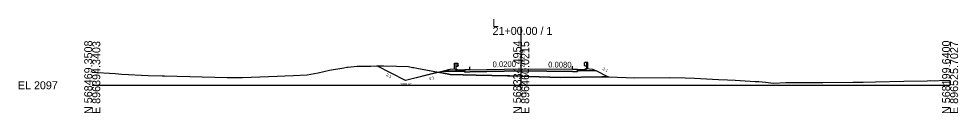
# Model space of a CAD drawing. Extents: x -26 to 1603, y -10 to 13527.
# Drawn here: x -25.7 to 302.8, y 8490.3 to 8523.1 of the extents above; entities that cross this region are included whole.
import ezdxf

# ---------------------------------------------------------------- set-up
doc = ezdxf.new("R2010")
doc.units = 0
for name, color, linetype in [('Default', 7, 'Continuous'), ('Exist XS Center Line Elevation Label', 7, 'Continuous'), ('Exist XS Ground Line', 7, 'Continuous'), ('Old_Level_3', 7, 'Continuous'), ('Old_Level_63', 7, 'Continuous'), ('Prop XS Ditch Slope Text', 7, 'Continuous'), ('Prop XS Ditch Standard Text', 7, 'Continuous'), ('Prop XS Dump Level', 7, 'Continuous'), ('Prop XS Earthwork Shape', 7, 'Continuous'), ('Prop XS EOT Tick Mark', 7, 'Continuous'), ('Prop XS Finish Grade', 7, 'Continuous'), ('Prop XS Finish Grade Earthwork', 7, 'Continuous'), ('Prop XS Finish Grade Paved Shoulder', 7, 'Continuous'), ('Prop XS Finish Grade Pavement', 7, 'Continuous'), ('Prop XS Side Slope Text', 7, 'Continuous'), ('Prop XS Subgrade Earthwork', 7, 'Continuous'), ('Prop XSC Text', 7, 'Continuous'), ('Typical Curb CELL', 7, 'Continuous')]:
    doc.layers.add(name, color=color, linetype=linetype)

msp = doc.modelspace()

# ---------------------------------------------------------------- linework, layer by layer
at = {"layer": 'Exist XS Ground Line'}
for p, q in [((82.97, 8505.32), (87.93, 8506.08)), ((87.93, 8506.08), (89.03, 8506.27)), ((89.03, 8506.27), (89.42, 8506.31)), ((89.42, 8506.31), (92.6, 8506.63)), ((92.6, 8506.63), (97.43, 8506.7)), ((97.43, 8506.7), (101.89, 8506.78)), ((101.89, 8506.78), (106.44, 8506.64)), ((106.44, 8506.64), (110.56, 8506.53)), ((110.56, 8506.53), (111.94, 8506.25)), ((111.94, 8506.25), (112.48, 8506.18)), ((112.48, 8506.18), (113.47, 8505.99)), ((113.47, 8505.99), (124.68, 8503.87)), ((0, 8504.61), (7.96, 8504.08)), ((7.96, 8504.08), (10.31, 8503.93)), ((10.31, 8503.93), (19.57, 8503.37)), ((19.57, 8503.37), (24.45, 8503.26)), ((24.45, 8503.26), (25.24, 8503.27)), ((25.24, 8503.27), (34.16, 8503.11)), ((34.16, 8503.11), (47.13, 8502.77)), ((47.13, 8502.77), (51.05, 8502.68)), ((51.05, 8502.68), (52.55, 8502.7)), ((52.55, 8502.7), (64.69, 8503.17)), ((64.69, 8503.17), (67.3, 8503.28)), ((67.3, 8503.28), (70.39, 8503.36)), ((70.39, 8503.36), (75.14, 8503.62)), ((75.14, 8503.62), (79, 8504.4)), ((79, 8504.4), (82.97, 8505.32)), ((124.68, 8503.87), (125.21, 8503.78)), ((125.21, 8503.78), (134.25, 8503.48)), ((134.25, 8503.48), (145.2, 8503.35)), ((145.2, 8503.35), (146.09, 8503.33)), ((146.09, 8503.33), (150, 8503.2)), ((150, 8503.2), (152.43, 8503.12)), ((152.43, 8503.12), (163.84, 8502.75)), ((163.84, 8502.75), (178.16, 8502.92)), ((178.16, 8502.92), (180.73, 8502.94)), ((180.73, 8502.94), (189.6, 8502.58)), ((189.6, 8502.58), (201.79, 8502.77)), ((201.79, 8502.77), (207.36, 8502.65)), ((207.36, 8502.65), (210.62, 8502.47)), ((210.62, 8502.47), (219.05, 8502.05)), ((219.05, 8502.05), (222.15, 8501.85)), ((222.15, 8501.85), (224.89, 8501.8)), ((224.89, 8501.8), (231.79, 8501.3)), ((231.79, 8501.3), (233.16, 8501.27)), ((233.16, 8501.27), (235.39, 8501.14)), ((235.39, 8501.14), (238.28, 8500.78)), ((238.28, 8500.78), (242.61, 8500.94)), ((242.61, 8500.94), (248.5, 8500.96)), ((248.5, 8500.96), (254.57, 8501.03)), ((254.57, 8501.03), (255.44, 8501.01)), ((255.44, 8501.01), (266.02, 8501.08)), ((266.02, 8501.08), (269.58, 8501.12)), ((269.58, 8501.12), (273.97, 8501.2)), ((273.97, 8501.2), (283.86, 8501.39)), ((283.86, 8501.39), (291.93, 8501.54)), ((291.93, 8501.54), (293.18, 8501.64)), ((293.18, 8501.64), (294.61, 8501.6)), ((294.61, 8501.6), (297.8, 8501.77)), ((297.8, 8501.77), (300, 8501.67))]:
    msp.add_line(p, q, dxfattribs=at)
at = {"layer": 'Old_Level_3'}
for p, q in [((126.69, 8505.62), (126.69, 8507.73)), ((126.69, 8507.73), (127.19, 8507.73)), ((127.19, 8507.73), (127.19, 8505.65)), ((127.19, 8507.73), (127.69, 8507.73)), ((127.69, 8506.59), (127.19, 8506.59)), ((127.69, 8507.73), (127.98, 8507.53)), ((127.98, 8507.41), (127.69, 8507.21)), ((127.69, 8507.21), (127.69, 8507.11)), ((127.69, 8507.11), (127.98, 8506.91)), ((127.98, 8506.79), (127.69, 8506.59)), ((127.98, 8507.53), (128.01, 8507.47)), ((128.01, 8507.47), (127.98, 8507.41)), ((127.98, 8506.91), (128.01, 8506.85)), ((128.01, 8506.85), (127.98, 8506.79)), ((172.02, 8507.72), (171.99, 8507.66)), ((171.99, 8507.66), (172.02, 8507.6)), ((172.02, 8507.11), (171.99, 8507.05)), ((171.99, 8507.05), (172.02, 8506.99)), ((172.31, 8507.92), (172.02, 8507.72)), ((172.02, 8507.6), (172.31, 8507.4)), ((172.31, 8507.31), (172.02, 8507.11)), ((172.02, 8506.99), (172.31, 8506.79)), ((172.81, 8507.92), (172.31, 8507.92)), ((172.31, 8507.4), (172.31, 8507.31)), ((172.31, 8506.79), (172.81, 8506.79)), ((173.31, 8507.92), (172.81, 8507.92)), ((172.81, 8507.92), (172.81, 8505.8)), ((173.31, 8505.77), (173.31, 8507.92))]:
    msp.add_line(p, q, dxfattribs=at)
at = {"layer": 'Old_Level_63'}
for p, q in [((150, 8500), (150, 8520.34)), ((0, 8500), (150, 8500)), ((150, 8500), (300, 8500))]:
    msp.add_line(p, q, dxfattribs=at)
at = {"layer": 'Prop XS Earthwork Shape'}
for points in [[(121.12, 8504.55), (109.6, 8501.67), (99.47, 8506.73), (101.89, 8506.78), (106.44, 8506.64), (110.56, 8506.53), (111.94, 8506.25), (112.48, 8506.18), (113.47, 8505.99)], [(127.32, 8504.98), (130.34, 8504.98), (130.35, 8504.61), (132, 8504.64), (150, 8505), (168, 8504.85), (169.66, 8504.82), (169.66, 8505.2), (172.68, 8505.13), (176.08, 8505.13), (180.46, 8502.94), (178.16, 8502.92), (163.84, 8502.75), (152.43, 8503.12), (150, 8503.2), (146.09, 8503.33), (145.2, 8503.35), (134.25, 8503.48), (125.21, 8503.78), (124.68, 8503.87), (121.12, 8504.55), (122.85, 8504.98)]]:
    msp.add_lwpolyline(points, close=True, dxfattribs=at)
at = {"layer": 'Prop XS EOT Tick Mark'}
for p, q in [((132, 8505.43), (132, 8506.43)), ((132, 8505.43), (132, 8506.43)), ((168, 8505.65), (168, 8506.65)), ((168, 8505.65), (168, 8506.65)), ((168, 8505.65), (168, 8506.65)), ((168, 8505.65), (168, 8506.65)), ((168, 8505.65), (168, 8506.65))]:
    msp.add_line(p, q, dxfattribs=at)
at = {"layer": 'Prop XS Finish Grade'}
for p, q in [((172.7, 8505.81), (175, 8505.67)), ((125, 8505.52), (122.85, 8504.98)), ((127.32, 8505.66), (125, 8505.52)), ((128.01, 8505.31), (127.32, 8505.66)), ((175, 8505.67), (176.08, 8505.13))]:
    msp.add_line(p, q, dxfattribs=at)
at = {"layer": 'Prop XS Finish Grade Earthwork'}
for p, q in [((109.6, 8501.67), (99.47, 8506.73)), ((122.85, 8504.98), (109.6, 8501.67)), ((176.08, 8505.13), (180.46, 8502.94))]:
    msp.add_line(p, q, dxfattribs=at)
at = {"layer": 'Prop XS Finish Grade Paved Shoulder'}
for p, q in [((132, 8505.43), (130.33, 8505.4)), ((168, 8505.65), (169.67, 8505.61))]:
    msp.add_line(p, q, dxfattribs=at)
at = {"layer": 'Prop XS Finish Grade Pavement'}
for p, q in [((132, 8505.43), (150, 8505.79)), ((150, 8505.79), (168, 8505.65))]:
    msp.add_line(p, q, dxfattribs=at)
at = {"layer": 'Prop XS Subgrade Earthwork'}
for p, q in [((127.32, 8504.98), (122.85, 8504.98)), ((127.32, 8504.98), (130.34, 8504.98)), ((130.35, 8504.61), (130.34, 8504.98)), ((132, 8504.64), (130.35, 8504.61)), ((150, 8505), (132, 8504.64)), ((168, 8504.85), (150, 8505)), ((168, 8504.85), (169.66, 8504.82)), ((169.66, 8505.2), (169.66, 8504.82)), ((169.66, 8505.2), (172.68, 8505.13)), ((172.68, 8505.13), (176.08, 8505.13))]:
    msp.add_line(p, q, dxfattribs=at)
at = {"layer": 'Typical Curb CELL'}
for p, q in [((172, 8505.48), (172.7, 8505.81)), ((172.68, 8505.13), (172.7, 8505.81)), ((127.32, 8504.98), (127.32, 8505.66)), ((128.01, 8505.31), (127.32, 8505.66)), ((127.32, 8504.98), (130.34, 8504.98)), ((127.36, 8505.28), (127.51, 8505.32)), ((127.49, 8505.23), (127.36, 8505.28)), ((127.51, 8505.32), (127.49, 8505.23)), ((128.03, 8505.2), (127.92, 8505.12)), ((127.92, 8505.12), (128.09, 8505.08)), ((130.33, 8505.4), (128.01, 8505.31)), ((128.09, 8505.08), (128.03, 8505.2)), ((128.77, 8505.25), (128.73, 8505.14)), ((128.73, 8505.14), (128.85, 8505.13)), ((128.85, 8505.13), (128.77, 8505.25)), ((129.28, 8505.2), (129.17, 8505.12)), ((129.17, 8505.12), (129.34, 8505.08)), ((129.34, 8505.08), (129.28, 8505.2)), ((130.02, 8505.25), (129.98, 8505.14)), ((129.98, 8505.14), (130.1, 8505.13)), ((130.1, 8505.13), (130.02, 8505.25)), ((130.34, 8505.4), (130.34, 8505.4)), ((130.34, 8504.98), (130.34, 8505.39)), ((169.66, 8505.2), (169.67, 8505.6)), ((172.68, 8505.13), (169.66, 8505.2)), ((169.67, 8505.61), (169.67, 8505.61)), ((169.68, 8505.61), (172, 8505.48)), ((169.9, 8505.34), (169.99, 8505.46)), ((170.02, 8505.35), (169.9, 8505.34)), ((169.99, 8505.46), (170.02, 8505.35)), ((170.67, 8505.27), (170.73, 8505.39)), ((170.83, 8505.31), (170.67, 8505.27)), ((170.73, 8505.39), (170.83, 8505.31)), ((171.15, 8505.31), (171.24, 8505.43)), ((171.27, 8505.32), (171.15, 8505.31)), ((171.24, 8505.43), (171.27, 8505.32)), ((171.91, 8505.25), (171.98, 8505.36)), ((172.08, 8505.28), (171.91, 8505.25)), ((171.98, 8505.36), (172.08, 8505.28)), ((172.5, 8505.48), (172.51, 8505.39)), ((172.65, 8505.43), (172.5, 8505.48)), ((172.51, 8505.39), (172.65, 8505.43))]:
    msp.add_line(p, q, dxfattribs=at)
for centre in [(127.39, 8505.36), (127.48, 8505.09), (127.6, 8505.14), (127.86, 8505.17), (127.88, 8505.12), (128.05, 8505.03), (128.08, 8505.14), (128.28, 8505.1), (128.32, 8505.21), (128.45, 8505.18), (128.48, 8505.06), (128.54, 8505.09), (128.73, 8505.09), (128.85, 8505.14), (128.94, 8505.13), (129.04, 8505.09), (129.1, 8505.23), (129.11, 8505.17), (129.13, 8505.12), (129.33, 8505.14), (129.52, 8505.1), (129.57, 8505.21), (129.62, 8505.18), (129.7, 8505.18), (129.73, 8505.06), (129.79, 8505.09), (129.85, 8505.27), (130.21, 8505.34), (130.25, 8505.22), (169.76, 8505.43), (169.8, 8505.56), (170.16, 8505.47), (170.22, 8505.29), (170.27, 8505.26), (170.31, 8505.39), (170.38, 8505.38), (170.43, 8505.41), (170.48, 8505.29), (170.67, 8505.33), (170.88, 8505.31), (170.9, 8505.36), (170.91, 8505.42), (170.96, 8505.27), (171.06, 8505.32), (171.15, 8505.32), (171.27, 8505.27), (171.47, 8505.27), (171.52, 8505.23), (171.56, 8505.36), (171.68, 8505.38), (171.73, 8505.27), (171.92, 8505.3), (171.95, 8505.2), (172.13, 8505.28), (172.15, 8505.33), (172.4, 8505.3), (172.52, 8505.24), (172.62, 8505.51)]:
    msp.add_circle(centre, 0.00802, dxfattribs=at)
for centre, start, end in [((130.33, 8505.39), 0, 92.048), ((169.68, 8505.6), 86.6704, 178.7184)]:
    msp.add_arc(centre, 0.0104, start, end, dxfattribs=at)

# ---------------------------------------------------------------- texts
at = {"layer": 'Default'}
for s, rotation, p in [('0.0200', 1.1458, (140.02, 8506.28)), ('0.0080', 359.5416, (159.43, 8506.23))]:
    msp.add_text(s, height=2, rotation=rotation, dxfattribs=at).set_placement(p)
at = {"layer": 'Exist XS Center Line Elevation Label'}
msp.add_text('2100.20', height=1, rotation=90, dxfattribs=at).set_placement((150.5, 8495.6))
at = {"layer": 'Old_Level_63'}
for s, p in [('L', (140, 8520.34)), ('21+00.00 / 1', (140, 8517.54)), ('EL 2097', (-26, 8498.6))]:
    msp.add_text(s, height=2.8, dxfattribs=at).set_placement(p)
for s, p in [('N 568469.3508', (0, 8490)), ('E 896394.3403', (2.8, 8490)), ('N 568334.4954', (150, 8490)), ('E 896460.0215', (152.8, 8490)), ('N 568199.6400', (300, 8490)), ('E 896525.7027', (302.8, 8490))]:
    msp.add_text(s, height=2.8, rotation=90, dxfattribs=at).set_placement(p)
at = {"layer": 'Prop XS Ditch Slope Text'}
msp.add_text('4:1', height=1, rotation=14.0351, dxfattribs=at).set_placement((117.86, 8501.74))
at = {"layer": 'Prop XS Ditch Standard Text'}
msp.add_text('2098.67', height=0.8, dxfattribs=at).set_placement((107.68, 8499.97))
at = {"layer": 'Prop XS Dump Level'}
msp.add_text('Case1', height=0.04, dxfattribs=at).set_placement((172, 8505.29))
at = {"layer": 'Prop XS Side Slope Text'}
for rotation, p in [(333.4443, (178.35, 8505.39)), (333.4369, (102.68, 8503.35))]:
    msp.add_text('2:1', height=1, rotation=rotation, dxfattribs=at).set_placement(p)
at = {"layer": 'Prop XSC Text'}
msp.add_text(' 2102.79', height=1.2, rotation=90, dxfattribs=at).set_placement((151.2, 8505.79))

doc.saveas('drawing.dxf')
